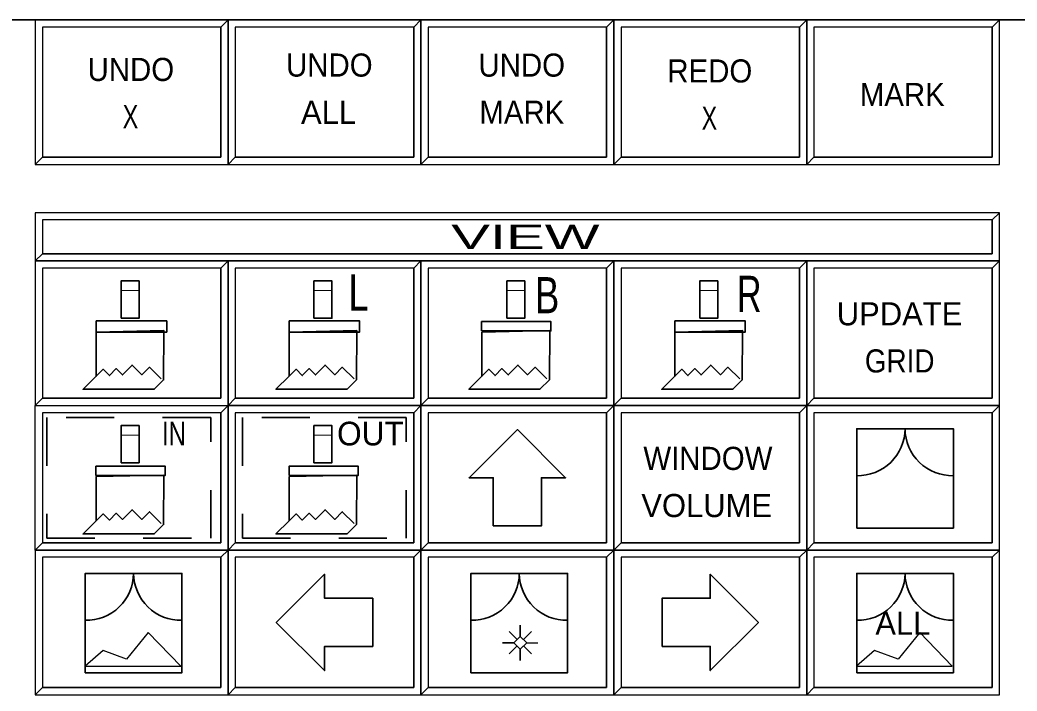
# Model space of a CAD drawing. Extents: x 95906.8 to 95923.6, y 90964.8 to 90972.8.
# Drawn here: x 95912.601 to 95914.669, y 90971.369 to 90972.762 of the extents above; entities that cross this region are included whole.
import ezdxf
from ezdxf.enums import TextEntityAlignment as Align

# ---------------------------------------------------------------- set-up
doc = ezdxf.new("R2010")
doc.units = 0
doc.header["$LTSCALE"] = 0.019
doc.linetypes.add('DOTTED', pattern=[1.5, 0.3, -1.2])
doc.linetypes.add('MEDIUM_DASHED', pattern=[4.5, 3, -1.5])
for name, color, linetype, lineweight in [('1', 7, 'Continuous', 25), ('11', 7, 'Continuous', 25), ('12', 7, 'Continuous', 25), ('2', 7, 'Continuous', 13), ('21', 7, 'Continuous', 25), ('3', 7, 'Continuous', 25), ('6', 7, 'Continuous', 35), ('7', 7, 'Continuous', 35)]:
    doc.layers.add(name, color=color, linetype=linetype, lineweight=lineweight)

msp = doc.modelspace()

# ---------------------------------------------------------------- linework, layer by layer
at = {"layer": '1'}
msp.add_line((95912.6323, 90971.6615), (95912.6323, 90971.9615), dxfattribs=at)
for points in [[(95912.6323, 90972.4617), (95913.0323, 90972.4617), (95913.0323, 90972.7617), (95912.6323, 90972.7617)], [(95913.0323, 90972.4617), (95913.4323, 90972.4617), (95913.4323, 90972.7617), (95913.0323, 90972.7617)], [(95913.4323, 90972.4617), (95913.8323, 90972.4617), (95913.8323, 90972.7617), (95913.4323, 90972.7617)], [(95913.8323, 90972.4617), (95914.2323, 90972.4617), (95914.2323, 90972.7617), (95913.8323, 90972.7617)], [(95914.2323, 90972.4617), (95914.6323, 90972.4617), (95914.6323, 90972.7617), (95914.2323, 90972.7617)], [(95912.6323, 90972.2617), (95914.6323, 90972.2617), (95914.6323, 90972.3617), (95912.6323, 90972.3617)], [(95912.6323, 90971.9617), (95913.0323, 90971.9617), (95913.0323, 90972.2617), (95912.6323, 90972.2617)], [(95913.0323, 90971.9617), (95913.4323, 90971.9617), (95913.4323, 90972.2617), (95913.0323, 90972.2617)], [(95913.4323, 90971.9617), (95913.8323, 90971.9617), (95913.8323, 90972.2617), (95913.4323, 90972.2617)], [(95913.8323, 90971.9617), (95914.2323, 90971.9617), (95914.2323, 90972.2617), (95913.8323, 90972.2617)], [(95914.2323, 90971.9617), (95914.6323, 90971.9617), (95914.6323, 90972.2617), (95914.2323, 90972.2617)], [(95913.0323, 90971.6617), (95913.4323, 90971.6617), (95913.4323, 90971.9617), (95913.0323, 90971.9617)], [(95913.4323, 90971.6617), (95913.8323, 90971.6617), (95913.8323, 90971.9617), (95913.4323, 90971.9617)], [(95913.8323, 90971.6617), (95914.2323, 90971.6617), (95914.2323, 90971.9617), (95913.8323, 90971.9617)], [(95914.2323, 90971.6617), (95914.6323, 90971.6617), (95914.6323, 90971.9617), (95914.2323, 90971.9617)], [(95912.6323, 90971.3617), (95913.0323, 90971.3617), (95913.0323, 90971.6617), (95912.6323, 90971.6617)], [(95913.0323, 90971.3617), (95913.4323, 90971.3617), (95913.4323, 90971.6617), (95913.0323, 90971.6617)], [(95913.4323, 90971.3617), (95913.8323, 90971.3617), (95913.8323, 90971.6617), (95913.4323, 90971.6617)], [(95913.8323, 90971.3617), (95914.2323, 90971.3617), (95914.2323, 90971.6617), (95913.8323, 90971.6617)], [(95914.2323, 90971.3617), (95914.6323, 90971.3617), (95914.6323, 90971.6617), (95914.2323, 90971.6617)]]:
    msp.add_lwpolyline(points, close=True, dxfattribs=at)
at = {"layer": '11'}
for points in [[(95912.6473, 90972.4767), (95913.0173, 90972.4767), (95913.0173, 90972.7467), (95912.6473, 90972.7467)], [(95913.0473, 90972.4767), (95913.4173, 90972.4767), (95913.4173, 90972.7467), (95913.0473, 90972.7467)], [(95913.4473, 90972.4767), (95913.8173, 90972.4767), (95913.8173, 90972.7467), (95913.4473, 90972.7467)], [(95913.8473, 90972.4767), (95914.2173, 90972.4767), (95914.2173, 90972.7467), (95913.8473, 90972.7467)], [(95914.2473, 90972.4767), (95914.6173, 90972.4767), (95914.6173, 90972.7467), (95914.2473, 90972.7467)], [(95914.2473, 90971.9767), (95914.6173, 90971.9767), (95914.6173, 90972.2467), (95914.2473, 90972.2467)], [(95913.4473, 90971.6767), (95913.8173, 90971.6767), (95913.8173, 90971.9467), (95913.4473, 90971.9467)], [(95913.8473, 90971.6767), (95914.2173, 90971.6767), (95914.2173, 90971.9467), (95913.8473, 90971.9467)], [(95912.6473, 90971.3767), (95913.0173, 90971.3767), (95913.0173, 90971.6467), (95912.6473, 90971.6467)], [(95913.0473, 90971.3767), (95913.4173, 90971.3767), (95913.4173, 90971.6467), (95913.0473, 90971.6467)], [(95913.4473, 90971.3767), (95913.8173, 90971.3767), (95913.8173, 90971.6467), (95913.4473, 90971.6467)], [(95913.8473, 90971.3767), (95914.2173, 90971.3767), (95914.2173, 90971.6467), (95913.8473, 90971.6467)], [(95914.2473, 90971.3767), (95914.6173, 90971.3767), (95914.6173, 90971.6467), (95914.2473, 90971.6467)]]:
    msp.add_lwpolyline(points, close=True, dxfattribs=at)
at = {"layer": '12'}
for points in [[(95912.6473, 90971.9767), (95913.0173, 90971.9767), (95913.0173, 90972.2467), (95912.6473, 90972.2467)], [(95913.0473, 90971.9767), (95913.4173, 90971.9767), (95913.4173, 90972.2467), (95913.0473, 90972.2467)], [(95913.4473, 90971.9767), (95913.8173, 90971.9767), (95913.8173, 90972.2467), (95913.4473, 90972.2467)], [(95913.8473, 90971.9767), (95914.2173, 90971.9767), (95914.2173, 90972.2467), (95913.8473, 90972.2467)], [(95912.6473, 90971.6767), (95913.0173, 90971.6767), (95913.0173, 90971.9467), (95912.6473, 90971.9467)], [(95913.0473, 90971.6767), (95913.4173, 90971.6767), (95913.4173, 90971.9467), (95913.0473, 90971.9467)], [(95914.2473, 90971.6767), (95914.6173, 90971.6767), (95914.6173, 90971.9467), (95914.2473, 90971.9467)]]:
    msp.add_lwpolyline(points, close=True, dxfattribs=at)
at = {"layer": '2'}
for points in [[(95912.6323, 90972.7617), (95912.6323, 90972.4617), (95912.6473, 90972.4767), (95912.6473, 90972.7467), (95913.0173, 90972.7467), (95913.0323, 90972.7617)], [(95913.0323, 90972.7617), (95913.0323, 90972.4617), (95913.0473, 90972.4767), (95913.0473, 90972.7467), (95913.4173, 90972.7467), (95913.4323, 90972.7617)], [(95913.4323, 90972.7617), (95913.4323, 90972.4617), (95913.4473, 90972.4767), (95913.4473, 90972.7467), (95913.8173, 90972.7467), (95913.8323, 90972.7617)], [(95913.8323, 90972.7617), (95913.8323, 90972.4617), (95913.8473, 90972.4767), (95913.8473, 90972.7467), (95914.2173, 90972.7467), (95914.2323, 90972.7617)], [(95914.2323, 90972.7617), (95914.2323, 90972.4617), (95914.2473, 90972.4767), (95914.2473, 90972.7467), (95914.6173, 90972.7467), (95914.6323, 90972.7617)], [(95912.6323, 90972.3617), (95912.6323, 90972.2617), (95912.6473, 90972.2767), (95912.6473, 90972.3467), (95914.6173, 90972.3467), (95914.6323, 90972.3617)], [(95912.6323, 90972.2617), (95912.6323, 90971.9617), (95912.6473, 90971.9767), (95912.6473, 90972.2467), (95913.0173, 90972.2467), (95913.0323, 90972.2617)], [(95913.0323, 90972.2617), (95913.0323, 90971.9617), (95913.0473, 90971.9767), (95913.0473, 90972.2467), (95913.4173, 90972.2467), (95913.4323, 90972.2617)], [(95913.4323, 90972.2617), (95913.4323, 90971.9617), (95913.4473, 90971.9767), (95913.4473, 90972.2467), (95913.8173, 90972.2467), (95913.8323, 90972.2617)], [(95913.8323, 90972.2617), (95913.8323, 90971.9617), (95913.8473, 90971.9767), (95913.8473, 90972.2467), (95914.2173, 90972.2467), (95914.2323, 90972.2617)], [(95914.2323, 90972.2617), (95914.2323, 90971.9617), (95914.2473, 90971.9767), (95914.2473, 90972.2467), (95914.6173, 90972.2467), (95914.6323, 90972.2617)], [(95912.6323, 90971.9617), (95912.6323, 90971.6617), (95912.6473, 90971.6767), (95912.6473, 90971.9467), (95913.0173, 90971.9467), (95913.0323, 90971.9617)], [(95913.0323, 90971.9617), (95913.0323, 90971.6617), (95913.0473, 90971.6767), (95913.0473, 90971.9467), (95913.4173, 90971.9467), (95913.4323, 90971.9617)], [(95913.4323, 90971.9617), (95913.4323, 90971.6617), (95913.4473, 90971.6767), (95913.4473, 90971.9467), (95913.8173, 90971.9467), (95913.8323, 90971.9617)], [(95913.8323, 90971.9617), (95913.8323, 90971.6617), (95913.8473, 90971.6767), (95913.8473, 90971.9467), (95914.2173, 90971.9467), (95914.2323, 90971.9617)], [(95914.2323, 90971.9617), (95914.2323, 90971.6617), (95914.2473, 90971.6767), (95914.2473, 90971.9467), (95914.6173, 90971.9467), (95914.6323, 90971.9617)], [(95912.6323, 90971.6617), (95912.6323, 90971.3617), (95912.6473, 90971.3767), (95912.6473, 90971.6467), (95913.0173, 90971.6467), (95913.0323, 90971.6617)], [(95913.0323, 90971.6617), (95913.0323, 90971.3617), (95913.0473, 90971.3767), (95913.0473, 90971.6467), (95913.4173, 90971.6467), (95913.4323, 90971.6617)], [(95913.4323, 90971.6617), (95913.4323, 90971.3617), (95913.4473, 90971.3767), (95913.4473, 90971.6467), (95913.8173, 90971.6467), (95913.8323, 90971.6617)], [(95913.8323, 90971.6617), (95913.8323, 90971.3617), (95913.8473, 90971.3767), (95913.8473, 90971.6467), (95914.2173, 90971.6467), (95914.2323, 90971.6617)], [(95914.2323, 90971.6617), (95914.2323, 90971.3617), (95914.2473, 90971.3767), (95914.2473, 90971.6467), (95914.6173, 90971.6467), (95914.6323, 90971.6617)]]:
    msp.add_lwpolyline(points, close=True, dxfattribs=at)
at = {"layer": '21'}
msp.add_lwpolyline([(95912.6473, 90972.2767), (95914.6173, 90972.2767), (95914.6173, 90972.3467), (95912.6473, 90972.3467)], close=True, dxfattribs=at)
at = {"layer": '3'}
for points in [[(95912.6323, 90972.4617), (95913.0323, 90972.4617), (95913.0323, 90972.7617), (95913.0173, 90972.7467), (95913.0173, 90972.4767), (95912.6473, 90972.4767)], [(95913.0323, 90972.4617), (95913.4323, 90972.4617), (95913.4323, 90972.7617), (95913.4173, 90972.7467), (95913.4173, 90972.4767), (95913.0473, 90972.4767)], [(95913.4323, 90972.4617), (95913.8323, 90972.4617), (95913.8323, 90972.7617), (95913.8173, 90972.7467), (95913.8173, 90972.4767), (95913.4473, 90972.4767)], [(95913.8323, 90972.4617), (95914.2323, 90972.4617), (95914.2323, 90972.7617), (95914.2173, 90972.7467), (95914.2173, 90972.4767), (95913.8473, 90972.4767)], [(95914.2323, 90972.4617), (95914.6323, 90972.4617), (95914.6323, 90972.7617), (95914.6173, 90972.7467), (95914.6173, 90972.4767), (95914.2473, 90972.4767)], [(95912.6323, 90972.2617), (95914.6323, 90972.2617), (95914.6323, 90972.3617), (95914.6173, 90972.3467), (95914.6173, 90972.2767), (95912.6473, 90972.2767)], [(95912.6323, 90971.9617), (95913.0323, 90971.9617), (95913.0323, 90972.2617), (95913.0173, 90972.2467), (95913.0173, 90971.9767), (95912.6473, 90971.9767)], [(95913.0323, 90971.9617), (95913.4323, 90971.9617), (95913.4323, 90972.2617), (95913.4173, 90972.2467), (95913.4173, 90971.9767), (95913.0473, 90971.9767)], [(95913.4323, 90971.9617), (95913.8323, 90971.9617), (95913.8323, 90972.2617), (95913.8173, 90972.2467), (95913.8173, 90971.9767), (95913.4473, 90971.9767)], [(95913.8323, 90971.9617), (95914.2323, 90971.9617), (95914.2323, 90972.2617), (95914.2173, 90972.2467), (95914.2173, 90971.9767), (95913.8473, 90971.9767)], [(95914.2323, 90971.9617), (95914.6323, 90971.9617), (95914.6323, 90972.2617), (95914.6173, 90972.2467), (95914.6173, 90971.9767), (95914.2473, 90971.9767)], [(95912.6323, 90971.6617), (95913.0323, 90971.6617), (95913.0323, 90971.9617), (95913.0173, 90971.9467), (95913.0173, 90971.6767), (95912.6473, 90971.6767)], [(95913.0323, 90971.6617), (95913.4323, 90971.6617), (95913.4323, 90971.9617), (95913.4173, 90971.9467), (95913.4173, 90971.6767), (95913.0473, 90971.6767)], [(95913.4323, 90971.6617), (95913.8323, 90971.6617), (95913.8323, 90971.9617), (95913.8173, 90971.9467), (95913.8173, 90971.6767), (95913.4473, 90971.6767)], [(95913.8323, 90971.6617), (95914.2323, 90971.6617), (95914.2323, 90971.9617), (95914.2173, 90971.9467), (95914.2173, 90971.6767), (95913.8473, 90971.6767)], [(95914.2323, 90971.6617), (95914.6323, 90971.6617), (95914.6323, 90971.9617), (95914.6173, 90971.9467), (95914.6173, 90971.6767), (95914.2473, 90971.6767)], [(95912.6323, 90971.3617), (95913.0323, 90971.3617), (95913.0323, 90971.6617), (95913.0173, 90971.6467), (95913.0173, 90971.3767), (95912.6473, 90971.3767)], [(95913.0323, 90971.3617), (95913.4323, 90971.3617), (95913.4323, 90971.6617), (95913.4173, 90971.6467), (95913.4173, 90971.3767), (95913.0473, 90971.3767)], [(95913.4323, 90971.3617), (95913.8323, 90971.3617), (95913.8323, 90971.6617), (95913.8173, 90971.6467), (95913.8173, 90971.3767), (95913.4473, 90971.3767)], [(95913.8323, 90971.3617), (95914.2323, 90971.3617), (95914.2323, 90971.6617), (95914.2173, 90971.6467), (95914.2173, 90971.3767), (95913.8473, 90971.3767)], [(95914.2323, 90971.3617), (95914.6323, 90971.3617), (95914.6323, 90971.6617), (95914.6173, 90971.6467), (95914.6173, 90971.3767), (95914.2473, 90971.3767)]]:
    msp.add_lwpolyline(points, close=True, dxfattribs=at)
at = {"layer": '6'}
for p, q in [((95913.6383, 90971.4827), (95913.6383, 90971.5061)), ((95913.6251, 90971.4694), (95913.6016, 90971.4694)), ((95913.6383, 90971.4562), (95913.6383, 90971.4328))]:
    msp.add_line(p, q, dxfattribs=at)
at = {"layer": '6', "linetype": 'MEDIUM_DASHED'}
for p, q in [((95913.6317, 90971.476), (95913.6151, 90971.4926)), ((95913.6449, 90971.476), (95913.6615, 90971.4926)), ((95913.6317, 90971.4628), (95913.6151, 90971.4463)), ((95913.6449, 90971.4628), (95913.6615, 90971.4463))]:
    msp.add_line(p, q, dxfattribs=at)
at = {"layer": '6', "lineweight": 25}
msp.add_line((95913.6515, 90971.4694), (95913.6749, 90971.4694), dxfattribs=at)
at = {"layer": '6'}
for points in [[(95912.8105, 90972.1428), (95912.8477, 90972.1428), (95912.8477, 90972.2202), (95912.8105, 90972.2202)], [(95913.2105, 90972.1428), (95913.2477, 90972.1428), (95913.2477, 90972.2202), (95913.2105, 90972.2202)], [(95913.6105, 90972.1428), (95913.6477, 90972.1428), (95913.6477, 90972.2202), (95913.6105, 90972.2202)], [(95914.0105, 90972.1428), (95914.0477, 90972.1428), (95914.0477, 90972.2202), (95914.0105, 90972.2202)], [(95912.7589, 90972.1371), (95912.905, 90972.1371), (95912.905, 90972.1142), (95912.7589, 90972.1142)], [(95913.1589, 90972.1371), (95913.305, 90972.1371), (95913.305, 90972.1142), (95913.1589, 90972.1142)], [(95913.5582, 90972.1166), (95913.7018, 90972.1166), (95913.7018, 90972.1359), (95913.5582, 90972.1359)], [(95913.9589, 90972.1371), (95914.105, 90972.1371), (95914.105, 90972.1142), (95913.9589, 90972.1142)], [(95912.7589, 90972.1142), (95912.7589, 90972.0225), (95912.7317, 90971.9953), (95912.8792, 90971.9953), (95912.8986, 90972.0147), (95912.8993, 90972.1171)], [(95913.1589, 90972.1142), (95913.1589, 90972.0225), (95913.1317, 90971.9953), (95913.2792, 90971.9953), (95913.2986, 90972.0147), (95913.2993, 90972.1171)], [(95913.5589, 90972.1142), (95913.5589, 90972.0225), (95913.5317, 90971.9953), (95913.6792, 90971.9953), (95913.6986, 90972.0147), (95913.6993, 90972.1171)], [(95913.9589, 90972.1142), (95913.9589, 90972.0225), (95913.9317, 90971.9953), (95914.0792, 90971.9953), (95914.0986, 90972.0147), (95914.0993, 90972.1171)], [(95912.8105, 90971.8428), (95912.8477, 90971.8428), (95912.8477, 90971.9202), (95912.8105, 90971.9202)], [(95913.2105, 90971.8428), (95913.2477, 90971.8428), (95913.2477, 90971.9202), (95913.2105, 90971.9202)], [(95913.5823, 90971.7117), (95913.5823, 90971.8117), (95913.5323, 90971.8117), (95913.6323, 90971.9117), (95913.7323, 90971.8117), (95913.6823, 90971.8117), (95913.6823, 90971.7117)], [(95914.336, 90971.7072), (95914.5365, 90971.7072), (95914.5365, 90971.9134), (95914.336, 90971.9134)], [(95912.7584, 90971.8165), (95912.902, 90971.8165), (95912.902, 90971.8358), (95912.7584, 90971.8358)], [(95913.1588, 90971.8165), (95913.3024, 90971.8165), (95913.3024, 90971.8358), (95913.1588, 90971.8358)], [(95912.7589, 90971.8142), (95912.7589, 90971.7225), (95912.7317, 90971.6953), (95912.8792, 90971.6953), (95912.8986, 90971.7147), (95912.8993, 90971.8171)], [(95913.1589, 90971.8142), (95913.1589, 90971.7225), (95913.1317, 90971.6953), (95913.2792, 90971.6953), (95913.2986, 90971.7147), (95913.2993, 90971.8171)], [(95912.736, 90971.4072), (95912.9365, 90971.4072), (95912.9365, 90971.6134), (95912.736, 90971.6134)], [(95913.3323, 90971.4617), (95913.2323, 90971.4617), (95913.2323, 90971.4117), (95913.1323, 90971.5117), (95913.2323, 90971.6117), (95913.2323, 90971.5617), (95913.3323, 90971.5617)], [(95913.536, 90971.4072), (95913.7365, 90971.4072), (95913.7365, 90971.6134), (95913.536, 90971.6134)], [(95913.9323, 90971.4617), (95914.0323, 90971.4617), (95914.0323, 90971.4117), (95914.1323, 90971.5117), (95914.0323, 90971.6117), (95914.0323, 90971.5617), (95913.9323, 90971.5617)], [(95914.336, 90971.4072), (95914.5365, 90971.4072), (95914.5365, 90971.6134), (95914.336, 90971.6134)]]:
    msp.add_lwpolyline(points, close=True, dxfattribs=at)
at = {"layer": '6', "lineweight": 13}
for points in [[(95912.8477, 90972.2202), (95912.8105, 90972.2202), (95912.8105, 90972.2001), (95912.8477, 90972.2001)], [(95913.2477, 90972.2202), (95913.2105, 90972.2202), (95913.2105, 90972.2001), (95913.2477, 90972.2001)], [(95913.6477, 90972.2202), (95913.6105, 90972.2202), (95913.6105, 90972.2001), (95913.6477, 90972.2001)], [(95914.0477, 90972.2202), (95914.0105, 90972.2202), (95914.0105, 90972.2001), (95914.0477, 90972.2001)], [(95912.8477, 90971.9202), (95912.8105, 90971.9202), (95912.8105, 90971.9001), (95912.8477, 90971.9001)], [(95913.2477, 90971.9202), (95913.2105, 90971.9202), (95913.2105, 90971.9001), (95913.2477, 90971.9001)], [(95913.6383, 90971.4562), (95913.6516, 90971.4695), (95913.6383, 90971.4827), (95913.625, 90971.4695)]]:
    msp.add_lwpolyline(points, close=True, dxfattribs=at)
at = {"layer": '6'}
for points in [[(95912.7589, 90972.0225), (95912.7732, 90972.0368), (95912.7861, 90972.0239), (95912.8004, 90972.0382), (95912.8133, 90972.0253), (95912.8334, 90972.0454), (95912.8534, 90972.0254), (95912.8691, 90972.0411), (95912.8935, 90972.0167)], [(95913.1589, 90972.0225), (95913.1732, 90972.0368), (95913.1861, 90972.0239), (95913.2004, 90972.0382), (95913.2133, 90972.0253), (95913.2334, 90972.0454), (95913.2534, 90972.0254), (95913.2691, 90972.0411), (95913.2935, 90972.0167)], [(95913.5589, 90972.0225), (95913.5732, 90972.0368), (95913.5861, 90972.0239), (95913.6004, 90972.0382), (95913.6133, 90972.0253), (95913.6334, 90972.0454), (95913.6534, 90972.0254), (95913.6691, 90972.0411), (95913.6935, 90972.0167)], [(95913.9589, 90972.0225), (95913.9732, 90972.0368), (95913.9861, 90972.0239), (95914.0004, 90972.0382), (95914.0133, 90972.0253), (95914.0334, 90972.0454), (95914.0534, 90972.0254), (95914.0691, 90972.0411), (95914.0935, 90972.0167)], [(95912.7589, 90971.7225), (95912.7732, 90971.7368), (95912.7861, 90971.7239), (95912.8004, 90971.7382), (95912.8133, 90971.7253), (95912.8334, 90971.7454), (95912.8534, 90971.7254), (95912.8691, 90971.7411), (95912.8935, 90971.7167)], [(95913.1589, 90971.7225), (95913.1732, 90971.7368), (95913.1861, 90971.7239), (95913.2004, 90971.7382), (95913.2133, 90971.7253), (95913.2334, 90971.7454), (95913.2534, 90971.7254), (95913.2691, 90971.7411), (95913.2935, 90971.7167)]]:
    msp.add_lwpolyline(points, dxfattribs=at)
at = {"layer": '6', "linetype": 'DOTTED'}
for points in [[(95912.9964, 90971.9366), (95912.6563, 90971.9366), (95912.6563, 90971.6862), (95912.9964, 90971.6862)], [(95913.402, 90971.9366), (95913.0619, 90971.9366), (95913.0619, 90971.6862), (95913.402, 90971.6862)]]:
    msp.add_lwpolyline(points, close=True, dxfattribs=at)
at = {"layer": '6', "lineweight": 25}
for points in [[(95912.7357, 90971.4207), (95912.9341, 90971.4207), (95912.8668, 90971.4909), (95912.8217, 90971.4351), (95912.773, 90971.4537)], [(95914.3357, 90971.4207), (95914.5341, 90971.4207), (95914.4668, 90971.4909), (95914.4217, 90971.4351), (95914.373, 90971.4537)]]:
    msp.add_lwpolyline(points, close=True, dxfattribs=at)
at = {"layer": '6'}
for centre, start, end in [((95914.3383, 90971.914), 268.6755, 359.6437), ((95914.5343, 90971.914), 180.3563, 271.3245), ((95912.7383, 90971.614), 268.6755, 359.6437), ((95912.9343, 90971.614), 180.3563, 271.3245), ((95913.5383, 90971.614), 268.6755, 359.6437), ((95913.7343, 90971.614), 180.3563, 271.3245), ((95914.3383, 90971.614), 268.6755, 359.6437), ((95914.5343, 90971.614), 180.3563, 271.3245)]:
    msp.add_arc(centre, 0.098, start, end, dxfattribs=at)
at = {"layer": '7'}
msp.add_lwpolyline([(95906.8323, 90972.7617), (95918.8323, 90972.7617), (95918.8323, 90964.7617), (95906.8323, 90964.7617)], close=True, dxfattribs=at)

# ---------------------------------------------------------------- texts
at = {"layer": '21', "width": 1.8}
msp.add_text('          VIEW         ', height=0.04999, dxfattribs=at).set_placement((95913.6322, 90972.2867), align=Align.CENTER)
at = {"layer": '6'}
for s, height, width, p in [('UNDO', 0.048, 0.95, (95912.8307, 90972.635)), ('UNDO', 0.048, 0.95, (95913.2423, 90972.6441)), ('UNDO', 0.048, 0.95, (95913.6414, 90972.644)), ('REDO', 0.048, 0.95, (95914.0314, 90972.6319)), ('MARK', 0.048, 0.95, (95914.4306, 90972.5829)), ('X', 0.048, 0.75, (95912.8299, 90972.537)), ('MARK', 0.048, 0.95, (95913.6416, 90972.5462)), ('X', 0.048, 0.75, (95914.0306, 90972.5339)), ('L', 0.075, 0.75, (95913.303, 90972.1586)), ('R', 0.075, 0.7, (95914.1132, 90972.1558)), ('B', 0.075, 0.75, (95913.6941, 90972.1531)), ('GRID', 0.048, 0.9, (95914.4252, 90972.0302)), ('IN', 0.0491, 0.75, (95912.92, 90971.8789)), ('WINDOW', 0.048, 0.95, (95914.0274, 90971.828))]:
    msp.add_text(s, height=height, dxfattribs=dict(at, width=width)).set_placement(p, align=Align.CENTER)
for s, height, p in [('ALL', 0.048, (95913.2407, 90972.5461)), ('UPDATE', 0.048, (95914.4249, 90972.128)), ('OUT', 0.0491, (95913.3276, 90971.8789)), ('VOLUME', 0.048, (95914.0249, 90971.7302)), ('ALL', 0.048, (95914.4318, 90971.4859))]:
    msp.add_text(s, height=height, dxfattribs=at).set_placement(p, align=Align.CENTER)

doc.saveas('drawing.dxf')
